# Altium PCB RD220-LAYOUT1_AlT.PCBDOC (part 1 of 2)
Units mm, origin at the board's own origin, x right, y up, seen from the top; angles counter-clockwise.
Board outline 250 x 145 mm, 4 copper layers (TOP, Mid-Layer 1, Mid-Layer 2, BOTTOM), stack 0.711 mm thick; 98 components, 44 nets, 237 pads, 371 vias.
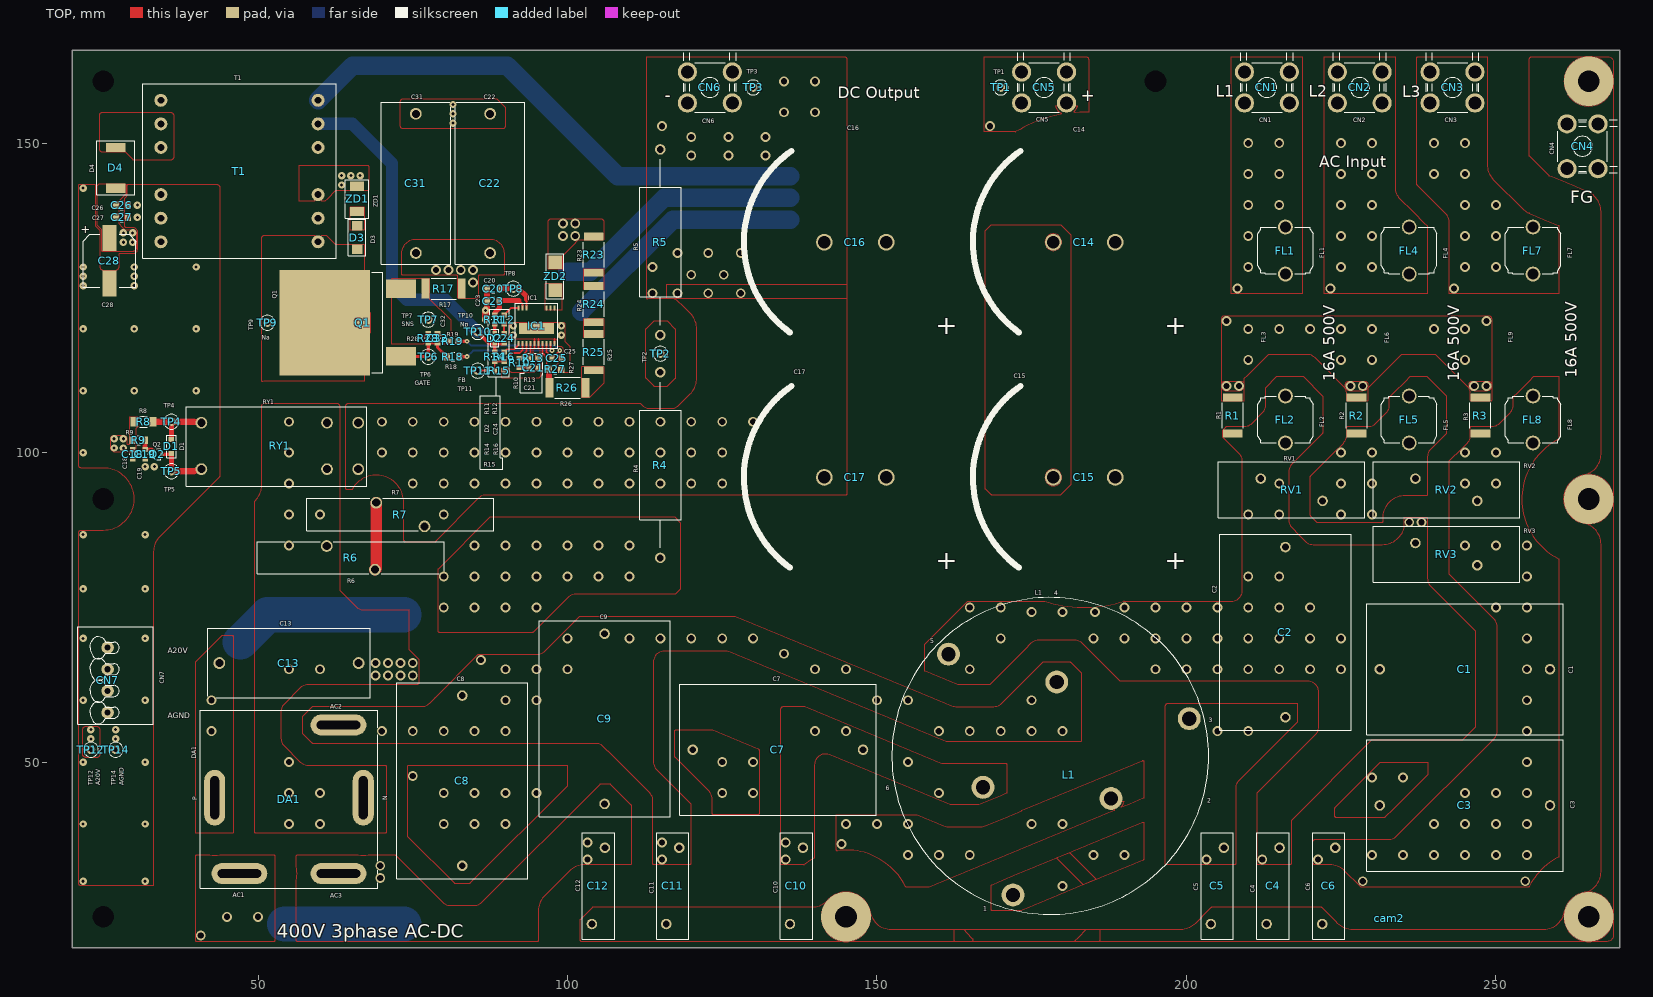
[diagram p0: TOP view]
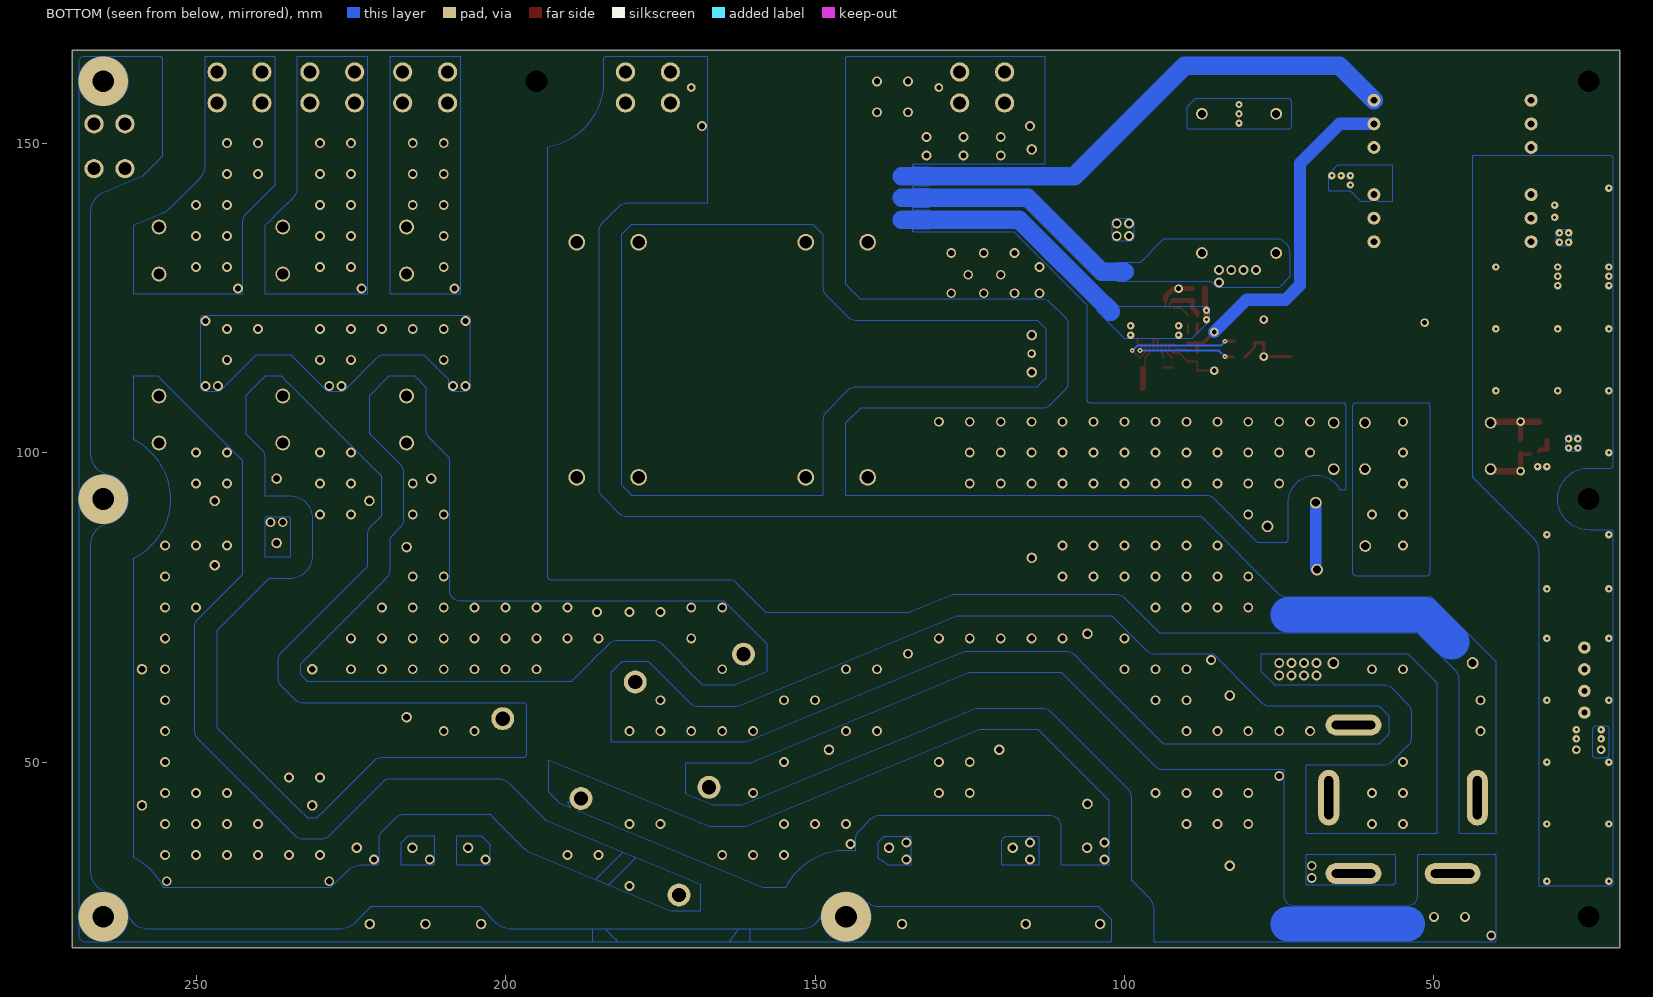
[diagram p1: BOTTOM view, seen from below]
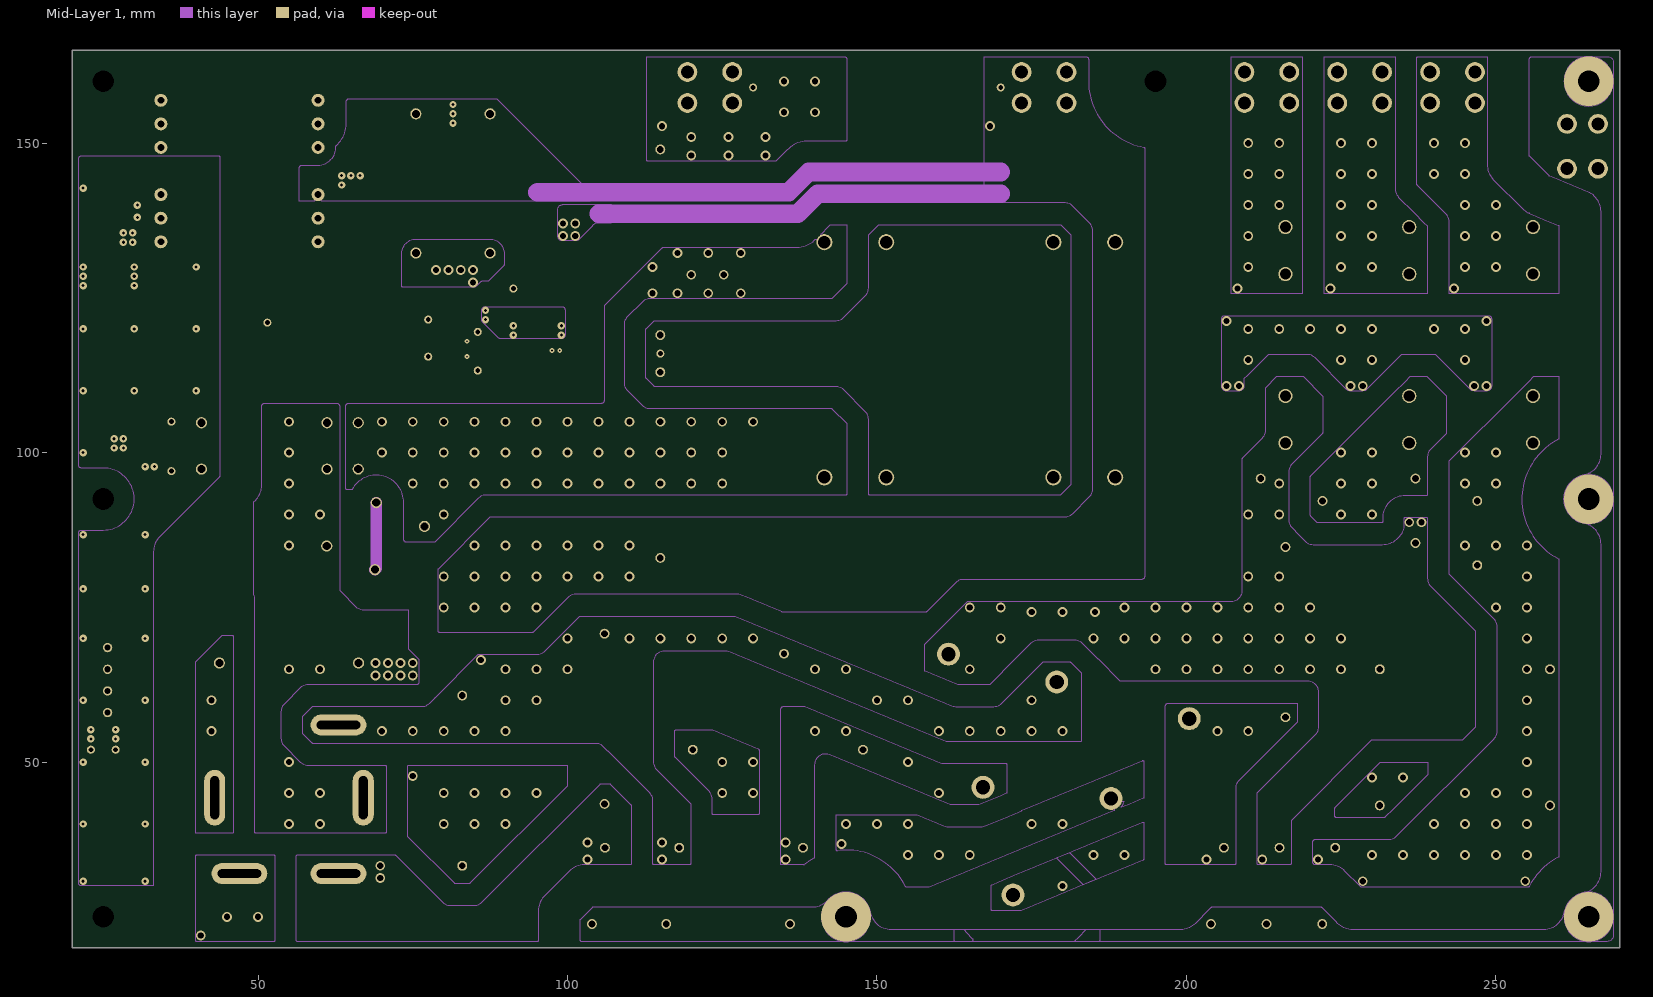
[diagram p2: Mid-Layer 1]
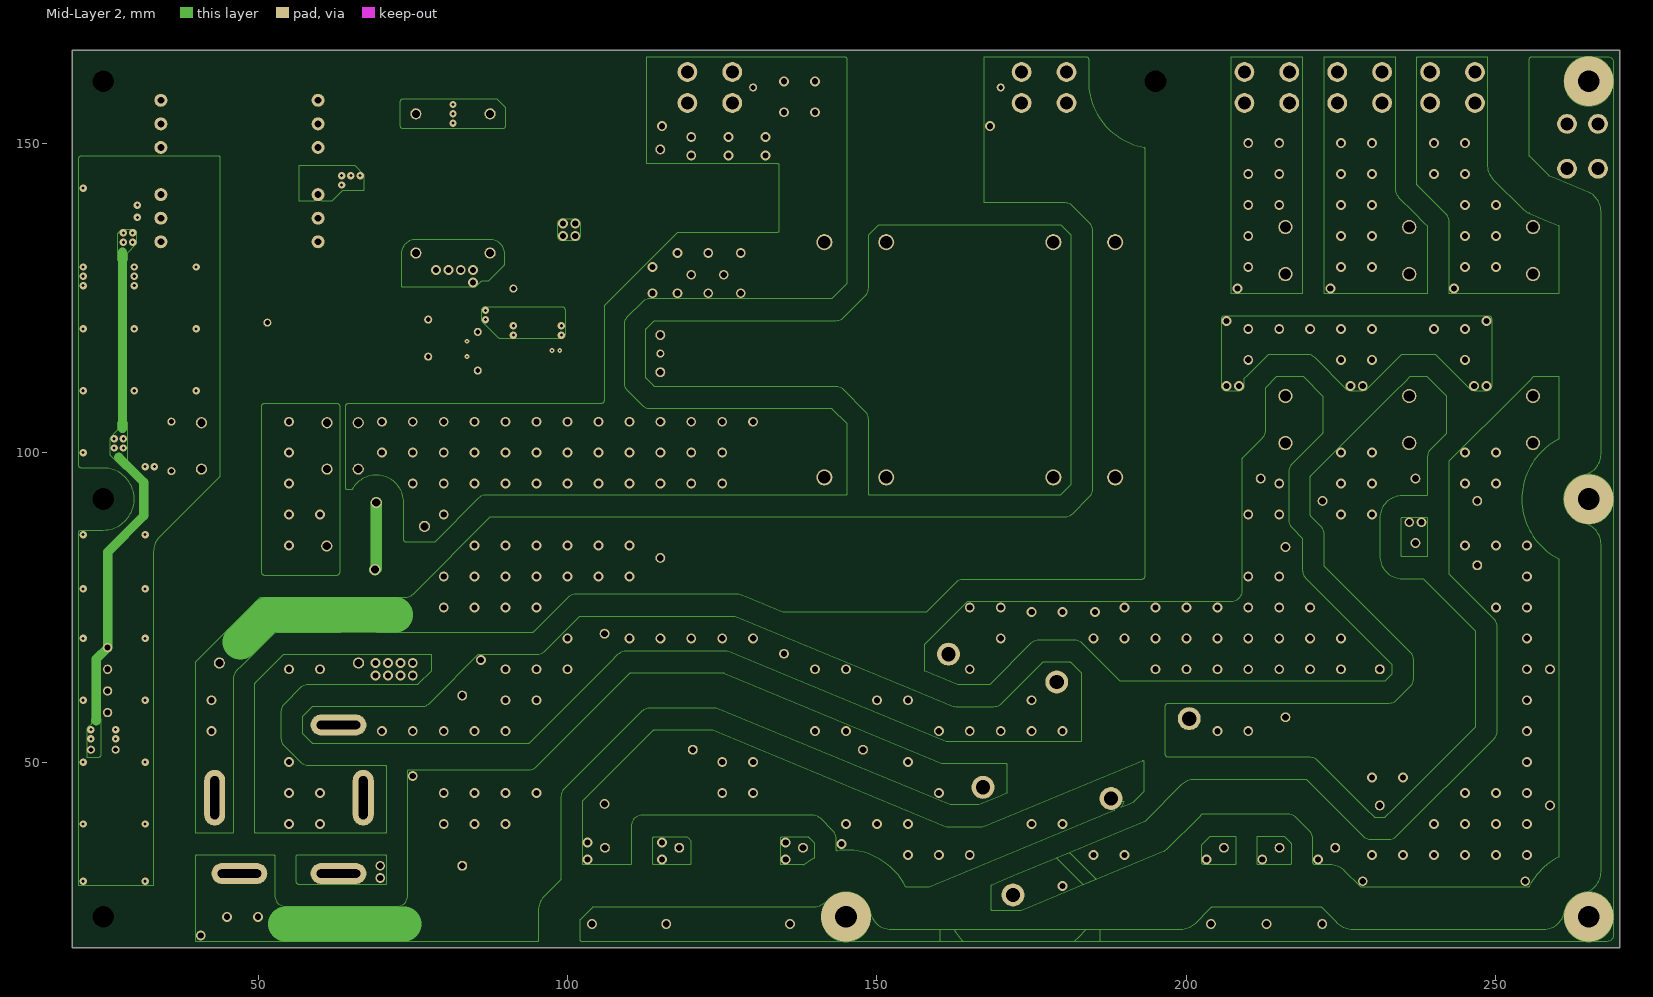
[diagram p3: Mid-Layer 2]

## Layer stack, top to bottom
Top Solder: solder mask 0.0102, Solder Resist, Dk 3.5
TOP: signal copper (thickness not stored)
Mid-Layer 1: signal copper 0.0356
Dielectric2: dielectric 0.32, FR-4, Dk 4.8
Mid-Layer 2: signal copper 0.0356
Dielectric3: dielectric 0.32, FR-4, Dk 4.8
BOTTOM: signal copper (thickness not stored)
Bottom Solder: solder mask 0.0102, Solder Resist, Dk 3.5

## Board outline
270,20 20,20 20,165 270,165

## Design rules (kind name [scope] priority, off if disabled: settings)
AssemblyTestPointUsage [All] p0: scope1count=1 scope1_0_kind=Board scope1_0_value=Board scope2count=1 scope2_0_kind=Board scope2_0_value=Board commentlength=0
AssemblyTestpoint [All] p0: scope1count=1 scope1_0_kind=Board scope1_0_value=Board scope2count=1 scope2_0_kind=Board scope2_0_value=Board commentlength=0
Clearance [All] p0: scope1count=1 scope1_0_kind=Board scope1_0_value=Board scope2count=1 scope2_0_kind=Board scope2_0_value=Board commentlength=0 gap=0.3
Clearance [All] p1: gap=0.3 ignorepadtopadclearanceinfootprint=TRUE except(0.5: Arc-Hole Track-Hole SMDPad-SMDPad SMDPad-Hole THPad-Hole Fill-Hole Poly-Hole Region-Hole Text-Hole; 0.75: Via-Hole; 1: SMDPad-THPad THPad-THPad)
ComponentClearance [All] p0: scope1count=1 scope1_0_kind=Board scope1_0_value=Board scope2count=1 scope2_0_kind=Board scope2_0_value=Board commentlength=0 gap=0.254 collisioncheckmode=3
DiffPairsRouting [All] p0: scope1count=1 scope1_0_kind=Board scope1_0_value=Board scope2count=1 scope2_0_kind=Board scope2_0_value=Board commentlength=0
FabricationTestPointUsage [All] p0: scope1count=1 scope1_0_kind=Board scope1_0_value=Board scope2count=1 scope2_0_kind=Board scope2_0_value=Board commentlength=0 valid=0 allowmultiple=FALSE
FabricationTestpoint [All] p0: scope1count=1 scope1_0_kind=Board scope1_0_value=Board scope2count=1 scope2_0_kind=Board scope2_0_value=Board commentlength=0 side=3 testpointundercomponent=TRUE minsize=1.016 maxsize=2.54 preferedsize=1.524 minholesize=0 maxholesize=1.016 preferedholesize=0.813 testpointgrid=0.025
FanoutControl Fanout_BGA [All] p0 off: scope1count=1 scope1_0_kind=Board scope1_0_value=Board scope2count=1 scope2_0_kind=Board scope2_0_value=Board commentlength=69 // Protel DXP Scope 1 Expression Was: IsBGA   Fanout_BGA (Default Rule)
FanoutControl Fanout_LCC [All] p0 off: scope1count=1 scope1_0_kind=Board scope1_0_value=Board scope2count=1 scope2_0_kind=Board scope2_0_value=Board commentlength=69 // Protel DXP Scope 1 Expression Was: IsLCC   Fanout_LCC (Default Rule)
FanoutControl Fanout_SOIC [All] p0 off: scope1count=1 scope1_0_kind=Board scope1_0_value=Board scope2count=1 scope2_0_kind=Board scope2_0_value=Board commentlength=71 // Protel DXP Scope 1 Expression Was: IsSOIC   Fanout_SOIC (Default Rule)
FanoutControl Fanout_Small [All] p0 off: scope1count=1 scope1_0_kind=Board scope1_0_value=Board scope2count=1 scope2_0_kind=Board scope2_0_value=Board commentlength=84 // Protel DXP Scope 1 Expression Was: (CompPinCount < 5)   Fanout_Small (Default Rule)
FanoutControl Fanout_Default [All] p0: scope1count=1 scope1_0_kind=Board scope1_0_value=Board scope2count=1 scope2_0_kind=Board scope2_0_value=Board commentlength=30 // Fanout_Default (Default Rule)
Height [All] p0: scope1count=1 scope1_0_kind=Board scope1_0_value=Board scope2count=1 scope2_0_kind=Board scope2_0_value=Board commentlength=0
HoleSize [All] p0: scope1count=1 scope1_0_kind=Board scope1_0_value=Board scope2count=1 scope2_0_kind=Board scope2_0_value=Board commentlength=0 absolutevalues=TRUE maxlimit=100 minlimit=0.001 maxpercent=80.000 minpercent=20.000
HoleSize [All] p1: absolutevalues=TRUE maxlimit=100 minlimit=0.001 maxpercent=80.000 minpercent=20.000
HoleToHoleClearance [All] p0: scope1count=1 scope1_0_kind=Board scope1_0_value=Board scope2count=1 scope2_0_kind=Board scope2_0_value=Board commentlength=0
HoleToHoleClearance [All] p1: gap=0.7 allowstackedmicrovias=FALSE
LayerPairs [All] p0: scope1count=1 scope1_0_kind=Board scope1_0_value=Board scope2count=1 scope2_0_kind=Board scope2_0_value=Board commentlength=0 enforce=TRUE
MinimumSolderMaskSliver [All] p0: scope1count=1 scope1_0_kind=Board scope1_0_value=Board scope2count=1 scope2_0_kind=Board scope2_0_value=Board commentlength=0
MinimumSolderMaskSliver [All] p1: minsoldermaskwidth=0.2
NetAntennae [All] p0: scope1count=1 scope1_0_kind=Board scope1_0_value=Board scope2count=1 scope2_0_kind=Board scope2_0_value=Board commentlength=0
NetAntennae [All] p1: netantennaetolerance=100
PasteMaskExpansion [All] p0: scope1count=1 scope1_0_kind=Board scope1_0_value=Board scope2count=1 scope2_0_kind=Board scope2_0_value=Board commentlength=0 expansion=0
PlaneClearance [All] p0: scope1count=1 scope1_0_kind=Board scope1_0_value=Board scope2count=1 scope2_0_kind=Board scope2_0_value=Board commentlength=0 clearance=0.001
PlaneClearance [All] p1: clearance=0.001
PlaneConnect [All] p0: scope1count=1 scope1_0_kind=Board scope1_0_value=Board scope2count=1 scope2_0_kind=Board scope2_0_value=Board commentlength=0 planeconnectstyle=Direct reliefexpansion=0.508 reliefentries=4 reliefconductorwidth=0.254 reliefairgap=0.254
PlaneConnect [All] p1: planeconnectstyle=Direct reliefexpansion=0.508 reliefentries=4 reliefconductorwidth=0.254 reliefairgap=0.254
PolygonConnect [All] p0: scope1count=1 scope1_0_kind=Board scope1_0_value=Board scope2count=1 scope2_0_kind=Board scope2_0_value=Board commentlength=0 connectstyle=Direct reliefconductorwidth=0.254 reliefentries=4 polygonreliefangle="90 Angle"
PolygonConnect [All] p1: connectstyle=Direct reliefconductorwidth=0.254 reliefentries=4 polygonreliefangle="90 Angle" airgapwidth=0.254
RoutingCorners [All] p0: scope1count=1 scope1_0_kind=Board scope1_0_value=Board scope2count=1 scope2_0_kind=Board scope2_0_value=Board commentlength=0 cornerstyle=45-Degree minsetback=2.54 maxsetback=2.54
RoutingLayers [All] p0: scope1count=1 scope1_0_kind=Board scope1_0_value=Board scope2count=1 scope2_0_kind=Board scope2_0_value=Board commentlength=0 top layer=Automatic mid layer 1=Automatic mid layer 2=Automatic bottom layer=Automatic
RoutingPriority [All] p0: scope1count=1 scope1_0_kind=Board scope1_0_value=Board scope2count=1 scope2_0_kind=Board scope2_0_value=Board commentlength=0
RoutingTopology [All] p0: scope1count=1 scope1_0_kind=Board scope1_0_value=Board scope2count=1 scope2_0_kind=Board scope2_0_value=Board commentlength=0 topology=Shortest
RoutingVias [All] p0: scope1count=1 scope1_0_kind=Board scope1_0_value=Board scope2count=1 scope2_0_kind=Board scope2_0_value=Board commentlength=0 holewidth=0.1 width=0.1 viastyle="Through Hole" minholewidth=0.001 minwidth=0.001 maxholewidth=100 maxwidth=100
RoutingVias [All] p1: holewidth=0.1 width=0.1 viastyle="Through Hole" minholewidth=0.001 minwidth=0.001 maxholewidth=100 maxwidth=100
ShortCircuit [All] p0: scope1count=1 scope1_0_kind=Board scope1_0_value=Board scope2count=1 scope2_0_kind=Board scope2_0_value=Board commentlength=0 allowed=FALSE
SilkToBoardRegionClearance [All] p0: scope1count=1 scope1_0_kind=Board scope1_0_value=Board scope2count=1 scope2_0_kind=Board scope2_0_value=Board commentlength=0
SilkToSilkClearance [All] p0: scope1count=1 scope1_0_kind=Board scope1_0_value=Board scope2count=1 scope2_0_kind=Board scope2_0_value=Board commentlength=0
SilkToSilkClearance [All] p1: silktosilkclearance=0.001
SilkToSolderMaskClearance [All] p0 off: scope1count=1 scope1_0_kind=Board scope1_0_value=Board scope2count=1 scope2_0_kind=Board scope2_0_value=Board commentlength=44 // Protel DXP Scope 1 Expression Was: IsPad
SilkToSolderMaskClearance [IsPad] p1: minsilkscreentomaskgap=0.1 clearancetoexposedcopper=TRUE
SolderMaskExpansion [All] p0: scope1count=1 scope1_0_kind=Board scope1_0_value=Board scope2count=1 scope2_0_kind=Board scope2_0_value=Board commentlength=0 expansion=0.001
SolderMaskExpansion [All] p1: expansion=0.001
UnRoutedNet [All] p0: scope1count=1 scope1_0_kind=Board scope1_0_value=Board scope2count=1 scope2_0_kind=Board scope2_0_value=Board commentlength=0
UnpouredPolygon [All] p0: scope1count=1 scope1_0_kind=Board scope1_0_value=Board scope2count=1 scope2_0_kind=Board scope2_0_value=Board commentlength=0
Width [All] p0: scope1count=1 scope1_0_kind=Board scope1_0_value=Board scope2count=1 scope2_0_kind=Board scope2_0_value=Board commentlength=0 maxlimit=1000 minlimit=2539.975 preferedwidth=0
Width [All] p1: maxlimit=1000 minlimit=2539.975 preferedwidth=0 toplayer_minwidth=0 midlayer1_minwidth=0 midlayer2_minwidth=0 bottomlayer_minwidth=0 minimp=50.000000 maximp=50.000000 favimp=50.000000
22 further rules are at their usual default settings.

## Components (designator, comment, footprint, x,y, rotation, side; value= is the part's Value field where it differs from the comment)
C1 "Ta-C0006DD" Ta-C0006DD 245,65 r180 top
C2 "Ta-C0006DD" Ta-C0006DD 216,71 r90 top
C3 "Ta-C0006DD" Ta-C0006DD 245,43 r180 top
C4 "Ta-C0001DD" Ta-C0001DD 214,30 r90 top
C5 "Ta-C0001DD" Ta-C0001DD 205,30 r90 top
C6 "Ta-C0001DD" Ta-C0001DD 223,30 r90 top
C7 "Ta-C0006DD" Ta-C0006DD 134,52 r0 top
C8 "Ta-C0006DD" Ta-C0006DD 83,47 r270 top
C9 "Ta-C0006DD" Ta-C0006DD 106,57 r90 top
C10 "Ta-C0001DD" Ta-C0001DD 137,30 r90 top
C11 "Ta-C0001DD" Ta-C0001DD 117,30 r90 top
C12 "Ta-C0001DD" Ta-C0001DD 105,30 r90 top
C13 "Ta-C0005DD" Ta-C0005DD 55,66 r180 top
C14 "Ta-CE0001DD" Ta-CE0001DD 183.5,134 r180 top
C15 "Ta-CE0001DD" Ta-CE0001DD 183.5,96 r180 top
C16 "Ta-CE0001DD" Ta-CE0001DD 146.5,134 r180 top
C17 "Ta-CE0001DD" Ta-CE0001DD 146.5,96 r180 top
C18 "Ta-C0001RR" Ta-C0001RR 29.75,99.75 r90 top
C19 "Ta-C0001RR" Ta-C0001RR 31.75,99.75 r90 top
C20 "Ta-C0002RR" Ta-C0002RR 88,126.5 r0 top
C21 "Ta-C0001RR" Ta-C0001RR 94.5,113.75 r180 top
C22 "Ta-C0005DD" Ta-C0005DD 87.5,143.5 r90 top
C23 "Ta-C0002RR" Ta-C0002RR 88,124.5 r0 top
C24 "Ta-C0001RR" Ta-C0001RR 89.75,118.5 r270 top
C25 "Ta-C0001RR" Ta-C0001RR 98.25,115.25 r180 top
C26 "Ta-C0002RR" Ta-C0002RR 28,140 r180 top
C27 "Ta-C0002RR" Ta-C0002RR 28,138 r180 top
C28 "Ta-CE0002RR" Ta-CE0002RR 26,131 r270 top
C31 "Ta-C0005DD" Ta-C0005DD 75.5,143.5 r90 top
C32 "Ta-C0001RR" Ta-C0001RR 79,118.5 r270 top
cam2 "Logo-Toshiba" Logo-Toshiba 232.8,24.8 r0 top
CN1 "Ta-CN0004DD(OT-005+OT-006)" Ta-CN0004DD(OT-005+OT-006) 213,159 r90 top
CN2 "Ta-CN0004DD(OT-005+OT-006)" Ta-CN0004DD(OT-005+OT-006) 228,159 r90 top
CN3 "Ta-CN0004DD(OT-005+OT-006)" Ta-CN0004DD(OT-005+OT-006) 243,159 r90 top
CN4 "Ta-CN0004DD(OT-005+OT-006)" Ta-CN0004DD(OT-005+OT-006) 264,149.5 r0 top
CN5 "Ta-CN0004DD(OT-005+OT-006)" Ta-CN0004DD(OT-005+OT-006) 177,159 r90 top
CN6 "Ta-CN0004DD(OT-005+OT-006)" Ta-CN0004DD(OT-005+OT-006) 123,159 r90 top
CN7 "Ta-CN0002DD" Ta-CN0002DD 27,64 r270 top
D1 "Ta-D0002RR" Ta-D0002RR 36,101 r270 top
D2 "Ta-D0001RR" Ta-D0001RR 88.25,118.5 r270 top
D3 "Ta-D0005RR" Ta-D0005RR 66,134.75 r270 top
D4 "Ta-D0006RR" Ta-D0006RR 27,146 r90 top
DA1 "Ta-DA0001DD" Ta-DA0001DD 55,44 r270 top
FL1 "Ta-FL0001DD" Ta-FL0001DD 216,119 r270 top
FL2 "Ta-FL0001DD" Ta-FL0001DD 216,119 r90 top
FL4 "Ta-FL0001DD" Ta-FL0001DD 236,119 r270 top
FL5 "Ta-FL0001DD" Ta-FL0001DD 236,119 r90 top
FL7 "Ta-FL0001DD" Ta-FL0001DD 256,119 r270 top
FL8 "Ta-FL0001DD" Ta-FL0001DD 256,119 r90 top
IC1 "Ta-IC0002RR_70" Ta-IC0002RR_70 95,120.5 r180 top
L1 "Ta-L0001DD" Ta-L0001DD 178,51 r180 top
Q1 "Ta-FET0003RR" Ta-FET0003RR 64.5,121 r90 top
Q2 "Ta-Q0001RR" Ta-Q0001RR 33.75,99.75 r270 top
R1 "Ta-R0007RR" Ta-R0007RR 207.5,106 r270 top
R2 "Ta-R0007RR" Ta-R0007RR 227.5,106 r270 top
R3 "Ta-R0007RR" Ta-R0007RR 247.5,106 r270 top
R4 "Ta-R0001DD" Ta-R0001DD 115,98 r270 top
R5 "Ta-R0001DD" Ta-R0001DD 115,134 r270 top
R6 "Ta-TH0001DD" Ta-TH0001DD 65,83 r0 top
R7 "Ta-TH0001DD" Ta-TH0001DD 73,90 r0 top
R8 "Ta-R0004RR" Ta-R0004RR 31.5,105 r0 top
R9 "Ta-R0003RR" Ta-R0003RR 30.75,102 r180 top
R10 "Ta-R0005RR" Ta-R0005RR 92.25,114.5 r270 top
R11 "Ta-R0005RR" Ta-R0005RR 88.25,121.5 r270 top
R12 "Ta-R0005RR" Ta-R0005RR 89.75,121.5 r90 top
R13 "Ta-R0005RR" Ta-R0005RR 94.5,115.25 r0 top
R14 "Ta-R0005RR" Ta-R0005RR 88.25,115.5 r270 top
R15 "Ta-R0005RR" Ta-R0005RR 89,113.25 r0 top
R16 "Ta-R0005RR" Ta-R0005RR 89.75,115.5 r90 top
R17 "Ta-R0007RR" Ta-R0007RR 80,126.5 r0 top
R18 "Ta-R0003RR" Ta-R0003RR 81.5,115.5 r0 top
R19 "Ta-R0005RR" Ta-R0005RR 81.5,118 r0 top
R23 "Ta-R0007RR" Ta-R0007RR 104.25,132 r270 top
R24 "Ta-R0007RR" Ta-R0007RR 104.25,124 r270 top
R25 "Ta-R0007RR" Ta-R0007RR 104.25,116.25 r270 top
R26 "Ta-R0007RR" Ta-R0007RR 100,110.5 r180 top
R27 "Ta-R0003RR" Ta-R0003RR 98,113.5 r0 top
R28 "Ta-R0005RR" Ta-R0005RR 77.5,118.5 r90 top
RV1 "Ta-RV0002DD" Ta-RV0002DD 217,94 r180 top
RV2 "Ta-RV0002DD" Ta-RV0002DD 242,94 r180 top
RV3 "Ta-RV0002DD" Ta-RV0002DD 242,83.6 r180 top
RY1 "Ta-RY0001DD" Ta-RY0001DD 53,101 r0 top
T1 "Ta-T0002DD" Ta-T0002DD 47,145.5 r90 top
TP1 "Ta-TP0001DD" Ta-TP0001DD 170,159 r0 top
TP2 "Ta-TP0001DD" Ta-TP0001DD 115,116 r0 top
TP3 "Ta-TP0001DD" Ta-TP0001DD 130,159 r0 top
TP4 "Ta-TP0001DD" Ta-TP0001DD 36,105 r90 top
TP5 "Ta-TP0001DD" Ta-TP0001DD 36,97 r90 top
TP6 "Ta-TP0001DD" Ta-TP0001DD 77.5,115.5 r180 top
TP7 "Ta-TP0001DD" Ta-TP0001DD 77.5,121.5 r180 top
TP8 "Ta-TP0001DD" Ta-TP0001DD 91.25,126.5 r180 top
TP9 "Ta-TP0001DD" Ta-TP0001DD 51.5,121 r90 top
TP10 "Ta-TP0001DD" Ta-TP0001DD 85.5,119.5 r180 top
TP11 "Ta-TP0001DD" Ta-TP0001DD 85.5,113.25 r180 top
TP12 "Ta-TP0001DD" Ta-TP0001DD 23,52 r90 top
TP14 "Ta-TP0001DD" Ta-TP0001DD 27,52 r90 top
ZD1 "Ta-D0004RR" Ta-D0004RR 66,141 r90 top
ZD2 "Ta-D0007RR" Ta-D0007RR 98,128.5 r270 top

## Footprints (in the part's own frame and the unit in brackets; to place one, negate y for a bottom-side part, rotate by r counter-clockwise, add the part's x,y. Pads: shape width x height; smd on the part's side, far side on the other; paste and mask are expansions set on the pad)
Logo-Toshiba [mm] "KC00080BKP"
Ta-C0001DD [mm] "KC00080BKP"
  round 1.7 / inner round 1.6 / far side round 1.7 hole 1.1 paste-1.9 mask+0: 1(-6.161,1.05) 2(6.161,-1.05)
  silkscreen extent -8.6,-2.6 8.6,2.6
Ta-C0001RR [mm] "KC00080BKP"
  rect 0.8x0.9 smd paste-1 mask+0: 1(-0.75,0) 2(0.75,0)
  silkscreen extent -0.06,-0.5 0.06,0.5
Ta-C0002RR [mm] "KC00080BKP"
  rect 1x1.2 smd paste-1.3 mask+0: 1(-1,0) 2(1,0)
  silkscreen extent -0.25,-0.72 0.25,0.72
Ta-C0005DD [mm] "KC00080BKP"
  round 1.9 / inner round 1.8 / far side round 1.9 hole 1.3 paste-2.1 mask+0: 1(-11.25,0) 2(11.25,0)
  silkscreen extent -13.1,-5.6 13.1,5.6
Ta-C0006DD [mm] "KC00080BKP"
  round 1.7 / inner round 1.6 / far side round 1.7 hole 1.1 paste-1.9 mask+0: 1(-13.75,0) 2(13.75,0)
  silkscreen extent -15.85,-10.6 15.85,10.6
Ta-CE0001DD [mm] "KC00080BKP"
  round 2.7 / inner round 2.6 / far side round 2.7 hole 2 paste-2.9 mask+0: 1(5,0) 2(-5,0)
  silkscreen extent 10.32,-14.74 18,14.56
Ta-CE0002RR [mm] "KC00080BKP"
  rect 4.2x2.2 smd paste-4.3 mask+0: 1(3.65,0) 2(-3.65,0)
  silkscreen extent -4.25,-4.25 4.25,4.25
Ta-CN0002DD [mm] "KC00080BKP"
  round 2 / inner round 1.5 / far side round 2 hole 1 paste-2.2 mask+0: 1(-4.5,-1.3) 2(-1,-1.3) 3(2.5,-1.3) 4(6,-1.3)
  silkscreen extent -7.85,-6.1 7.85,6.1
Ta-CN0004DD(OT-005+OT-006) [mm] "KC00080BKP"
  round 3.1 / inner round 3.2 / far side round 3.1 hole 2.1 paste-3.3 mask+0: 1(-2.5,-3.625) 2(2.5,-3.625) 3(2.5,3.625) 4(-2.5,3.625)
  silkscreen extent -4,-4.25 5.6,4.25
Ta-D0001RR [mm] "KC00080BKP"
  rect 0.6x0.8 smd paste-0.9 mask+0: A(0.85,0) C(-0.85,0)
  silkscreen extent -1.43,-0.67 1.42,0.68
Ta-D0002RR [mm] "KC00080BKP"
  rect 0.8x0.9 smd paste-1 mask+0: A(1.15,0) C(-1.15,0)
  silkscreen extent -1.85,-0.75 1.85,0.75
Ta-D0004RR [mm] "KC00080BKP"
  rect 1.52x2.2 smd paste-2.3 mask+0: A(2.035,0) C(-2.035,0)
  silkscreen extent -3.1,-1.91 3.1,1.91
Ta-D0005RR [mm] "KC00080BKP"
  rect 1.52x1.68 smd paste-1.78 mask+0: A(1.88,0) C(-1.88,0)
  silkscreen extent -2.94,-1.43 2.94,1.43
Ta-D0006RR [mm] "KC00080BKP"
  rect 1.52x3.2 smd paste-3.3 mask+0: A(3.305,0) C(-3.305,0)
  silkscreen extent -4.37,-3.05 4.37,3.05
Ta-D0007RR [mm] "KC00080BKP"
  rect 2.2x2.21 smd paste-2.31 mask+0: A(2.25,0) C(-2.25,0)
  silkscreen extent -3.65,-1.4 3.65,1.41
Ta-DA0001DD [mm] "KC00080BKP"
  oval 3.4x9 hole 1.4 slot 7 at 90 deg paste-9.2 mask+0: AC1(12,-8) AC2(-12,8) AC3(12,8)
  oval 9x3.4 hole 1.4 slot 7 at 0 deg paste-9.2 mask+0: N(-0.25,12) P(-0.25,-12)
  silkscreen extent -14.35,-14.35 14.35,14.35
Ta-FET0003RR [mm] "KC00080BKP"
  rect 17x14.6 smd paste-17.1 mask+0: D(0,3.7)
  rect 3x4.8 smd paste-4.9 mask+0: G(-5.45,-8.6) S(5.45,-8.6)
  silkscreen extent -8.11,-5.68 8.11,-3.9
Ta-FL0001DD [mm] "KC00080BKP"
  round 2.4 / inner round 2.3 / far side round 2.4 hole 1.8 paste-2.6 mask+0: 1(-17.45,0) 2(-9.85,0)
  silkscreen extent -17.4,-4.49 -9.9,4.49
Ta-IC0002RR_70 [mm] "KC00080BKP"
  rect 0.35x0.8 smd paste-0.9 mask+0: 1(-2.925,-2.9) 2(-2.275,-2.9) 3(-1.625,-2.9) 8(1.625,-2.9) 9(2.275,-2.9) 10(2.925,-2.9) 11(2.925,2.9) 12(2.275,2.9) 13(1.625,2.9) 14(0.975,2.9) 15(0.325,2.9) 16(-0.325,2.9) 17(-0.975,2.9) 18(-1.625,2.9) 19(-2.275,2.9) 20(-2.925,2.9)
  rect 5.68x1.78 smd paste-5.78 mask+0: 21(0,0.47)
  silkscreen extent -3.45,-3.65 3.45,3.65
Ta-L0001DD [mm] "KC00080BKP"
  round 3.7 hole 2.3 paste-3.9 mask+0: 1(6.018,22.458) 2(-9.83,6.883) 3(-22.458,-6.018) 4(-1.046,-11.954) 5(16.44,-16.44) 6(10.876,5.071)
  silkscreen extent -25.6,-25.6 25.6,25.6
Ta-Q0001RR [mm] "KC00080BKP"
  rect 0.6x0.6 smd paste-0.7 mask+0: B(-0.5,-0.7) C(0,0.7) E(0.5,-0.7)
  silkscreen extent -0.9,-0.13 0.9,0.5
Ta-R0001DD [mm] "KC00080BKP"
  round 1.7 / inner round 1.6 / far side round 1.7 hole 1.1 paste-1.9 mask+0: 1(-15,0) 2(15,0)
  silkscreen extent -13.4,-3.35 13.4,3.35
Ta-R0003RR [mm] "KC00080BKP"
  rect 1x1.2 smd paste-1.3 mask+0: 1(-1,0) 2(1,0)
  silkscreen extent -0.25,-0.72 0.25,0.72
Ta-R0004RR [mm] "KC00080BKP"
  rect 1.2x1.6 smd paste-1.7 mask+0: 1(-1.5,0) 2(1.5,0)
  silkscreen extent -0.63,-0.9 0.63,0.9
Ta-R0005RR [mm] "KC00080BKP"
  rect 0.8x0.9 smd paste-1 mask+0: 1(-0.75,0) 2(0.75,0)
  silkscreen extent -0.06,-0.5 0.06,0.5
Ta-R0007RR [mm] "KC00080BKP"
  rect 1.25x3.2 smd paste-3.3 mask+0: 1(-2.925,0) 2(2.925,0)
  silkscreen extent -2.03,-1.7 2.03,1.7
Ta-RV0002DD [mm] "KC00080BKP"
  round 1.7 / inner round 1.6 / far side round 1.7 hole 1.1 paste-1.9 mask+0: 1(-5,1.8) 2(5,-1.8)
  silkscreen extent -11.85,-4.5 11.85,4.5
Ta-RY0001DD [mm] "KC00080BKP"
  round 1.9 / inner round 1.8 / far side round 1.9 hole 1.3 paste-2.1 mask+0: 11-1(8.15,3.83) 11-2(8.15,-3.67) 14-1(13.19,3.83) 14-2(13.19,-3.67) A1(-12.15,3.83) A2(-12.15,-3.67)
  silkscreen extent -14.6,-6.45 14.6,6.45
Ta-T0002DD [mm] "KC00080BKP"
  round 2.1 hole 1.1 paste-2.3 mask+0: 1(-11.43,-12.7) 2(-7.62,-12.7) 3(-3.81,-12.7) 4(3.81,-12.7) 5(7.62,-12.7) 6(11.43,-12.7) 7(11.43,12.7) 8(7.62,12.7) 9(3.81,12.7) 10(-3.81,12.7) 11(-7.62,12.7) 12(-11.43,12.7)
  silkscreen extent -14.1,-15.6 14.1,15.6
Ta-TH0001DD [mm] "KC00080BKP"
  round 1.9 / inner round 1.8 / far side round 1.9 hole 1.3 paste-2.1 mask+0: 1(-3.9,1.91) 2(3.9,-1.91)
  silkscreen extent -15.1,-2.6 15.1,2.6
Ta-TP0001DD [mm] "KC00080BKP"
  round 1.4 / inner round 1.3 / far side round 1.4 hole 0.8 paste-1.6 mask+0: 1(0,0)
  silkscreen extent -1.2,-1.2 1.2,1.2

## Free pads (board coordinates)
  round 0 hole 3.5 unplated paste-3.5 mask+0: ""(25,25) ""(25,92.5) ""(25,160) ""(195,160)

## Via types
v1: diameter 1.6, hole 1, TOP to BOTTOM, 305 vias
v2: diameter 1.2, hole 0.5, TOP to BOTTOM, 58 vias
v3: diameter 8, hole 3.5, TOP to BOTTOM, 4 vias
v4: diameter 0.8, hole 0.3, TOP to BOTTOM, 4 vias

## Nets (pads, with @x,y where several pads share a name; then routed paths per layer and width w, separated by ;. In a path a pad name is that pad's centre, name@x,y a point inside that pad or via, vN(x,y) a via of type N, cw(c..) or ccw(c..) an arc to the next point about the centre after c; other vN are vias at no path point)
GND_A: C18.1 C19.1 C26.1 C27.1 C28.1 CN7.4 Q2.E T1.10 T1.11 TP14.1
  other v2: 21.75,30.75 31.75,30.75 21.75,40 31.75,40 21.75,50 31.75,50 27,53.75 27,55.25 21.75,60 31.75,60 21.75,70 31.75,70 21.75,78 31.75,78 21.75,86.75 31.75,86.75 31.75,97.75 33.25,97.75 21.75,100 21.75,110 30,110 40,110 21.75,120 30,120 40,120 21.75,127 30,127 21.75,128.5 30,128.5 21.75,130 30,130 40,130 30.5,138 30.5,140 21.75,142.75
GND_DC: C16.1 C17.1 C20.1 C21.1 C22.1 C23.1 C25.1 C31.1 CN6.1 CN6.2 CN6.3 CN6.4 IC1.15 IC1.16 IC1.20 IC1.21 R5.1 R7.2 R13.2 R15.2 R17.2 R27.2 RY1.14-1 RY1.14-2 T1.6 TP3.1 | length 176
  TOP w0.3: 94.675,116.8 IC1.15@94.675,117.6 94.675,118.4 ; 95.325,116.8 IC1.16@95.325,117.6 95.325,118.4 ; IC1.20@97.925,117.6 97.925,118.4
  TOP w1: v2(86.75,123) 87,123.25 C23.1@87,124.5 C20.1@87,126.5
  TOP w1.1: v2(86.75,121.5) v2(86.75,123)
  BOTTOM w3: T1.6@59.7,156.93 65.27,162.5 90.286,162.5 108.136,144.65 136,144.65 ; 100,129.2 103.652,129.2 115.602,141.15 136,141.15 ; 102.201,122.799 117.052,137.65 136,137.65
  other v1: 80,90 75,95 80,95 85,95 90,95 95,95 100,95 105,95 110,95 115,95 120,95 125,95 70,100 75,100 80,100 85,100 90,100 95,100 100,100 105,100 110,100 115,100 120,100 125,100 70,105 75,105 80,105 85,105 90,105 95,105 100,105 105,105 110,105 115,105 120,105 125,105 130,105 113.75,125.75 117.75,125.75 122.75,125.75 128,125.75 84.75,127.5 120,128.75 125.25,128.75 78.75,129.5 80.75,129.5 82.75,129.5 84.75,129.5 113.75,130 117.75,132.25 122.75,132.25 128,132.25 120,148 126,148 132,148 120,151 126,151 132,151 115.25,152.75 135,155 140,155 135,160 140,160
  other v2: 91.25,119 99,119 91.25,120.5 99,120.5
GND_F: C4.1 C5.1 C6.1 C10.1 C11.1 C12.1 CN4.1 CN4.2 CN4.3 CN4.4
  other v3: 145,25 265,25 265,92.5 265,160
L1: CN1.1 CN1.2 CN1.3 CN1.4 FL1.1 FL1.2
  other v1: 208.25,126.5 210,130 210,135 210,140 215,140 210,145 215,145 210,150 215,150
L1f: C1.2 C2.2 C4.2 FL2.1 FL2.2 L1.5 R1.2 RV1.2 RV3.2
  other v1: 212.25,34.25 165,65 195,65 200,65 205,65 210,65 215,65 220,65 225,65 170,70 185,70 190,70 195,70 200,70 205,70 210,70 215,70 220,70 225,70 175,74.25 180,74.25 185.25,74.25 165,75 170,75 190,75 195,75 200,75 205,75 210,75 215,75 220,75 210,80 215,80 236,88.75 238,88.75 210,90 215,90 215,95
L1r: C7.2 C8.2 C10.2 DA1.AC1 L1.6 | length 38.4
  Mid-Layer 2 w5.7: 54.5,23.85 73.6,23.85
  BOTTOM w5.7: 54.3,23.85 73.6,23.85
  other v1: 40.75,22 45,25 50,25 135.25,34.25 135.25,37 80,40 85,40 90,40 80,45 85,45 90,45 95,45 160,45 75,47.75 155,50 140,55 145,55
L2: CN2.1 CN2.2 CN2.3 CN2.4 FL4.1 FL4.2
  other v1: 223.25,126.5 225,130 230,130 225,135 230,135 225,140 230,140 225,145 230,145 225,150 230,150
L2f: C2.1 C3.2 C5.2 FL5.1 FL5.2 L1.3 R2.2 RV1.1 RV2.2
  other v1: 203.25,34.25 230,47.5 235,47.5 205,55 210,55 225,90 230,90 225,95 230,95 225,100 230,100
L2r: C8.1 C9.2 C11.2 DA1.AC2 L1.4
  other v1: 115.25,34.25 115.25,37 70,55 75,55 80,55 85,55 90,55 160,55 165,55 170,55 175,55 180,55 90,60 95,60 150,60 155,60 175,60 90,65 95,65 100,65 140,65 145,65 86,66.5 135,67.5 100,70 110,70 115,70 120,70 125,70 130,70
L3: CN3.1 CN3.2 CN3.3 CN3.4 FL7.1 FL7.2
  other v1: 243.25,126.5 245,130 250,130 245,135 250,135 245,140 250,140 240,145 245,145 240,150 245,150
L3f: C1.1 C3.1 C6.2 FL8.1 FL8.2 L1.1 R3.2 RV2.1 RV3.1
  other v1: 180,30 228.5,30.75 254.75,30.75 221.25,34.25 185,35 190,35 230,35 235,35 240,35 245,35 250,35 255,35 240,40 245,40 250,40 255,40 245,45 250,45 255,45 255,50 255,55 255,60 255,65 255,70 250,75 255,75 255,80 245,85 250,85 255,85 245,95 250,95 245,100 250,100
L3r: C7.1 C9.1 C12.2 DA1.AC3 L1.2
  other v1: 69.75,31.25 69.75,33.25 103.25,34.25 155,35 160,35 165,35 144.25,36.75 103.25,37 145,40 150,40 155,40 175,40 180,40 125,45 130,45 125,50 130,50
M: C14.1 C15.1 C16.2 C17.2 R4.1 R5.2 TP2.1
RDIS: R1.1 R2.1 R3.1
  other v1: 206.5,110.75 208.5,110.75 226.5,110.75 228.5,110.75 246.5,110.75 248.5,110.75 210,115 225,115 230,115 245,115 210,120 215,120 220,120 225,120 230,120 240,120 245,120 206.5,121.25 248.5,121.25
SIGN0021: C20.2 IC1.8 TP8.1 | length 6.8
  TOP w0.3: IC1.8@93.375,123.4 93.375,124.718
  TOP w0.8: C20.2@89,126.5 TP8.1@91.25,126.5 92.15,126.5 93.375,125.275 93.375,124.718
SIGN0023: IC1.13 R10.1 | length 2.8
  TOP w0.3: R10.1@92.25,115.25 93.375,116.375 IC1.13@93.375,117.6
SIGN0024: C21.2 R10.2 | length 1.5
  TOP w0.3: R10.2@92.25,113.75 C21.2@93.75,113.75
SIGN0029: C23.2 IC1.9 R11.1 | length 7.3
  TOP w0.3: 92.175,124.6 92.725,124.05 IC1.9@92.725,123.4
  TOP w0.8: R11.1@88.25,122.25 88.25,122.561 89,123.311 C23.2@89,124.5 89,124.6 92.175,124.6
SIGN00121: R6.2 R7.1 | length 43.6
  TOP w1.9: R6.2@68.9,81.09 69.1,81.29 R7.1@69.1,91.91
  Mid-Layer 1 w1.9: R6.2@68.9,81.09 69.1,81.29 R7.1@69.1,91.91
  Mid-Layer 2 w1.9: R6.2@68.9,81.09 69.1,81.29 R7.1@69.1,91.91
  BOTTOM w1.9: R6.2@68.9,81.09 69.1,81.29 R7.1@69.1,91.91
SIGN00122: C13.1 DA1.N R6.1 RY1.11-1 RY1.11-2
  other v1: 55,40 60,40 55,45 60,45 55,50 69,64 71,64 73,64 75,64 55,65 60,65 69,66 71,66 73,66 75,66 55,85 55,90 60,90 55,95 55,100 55,105
SIGN00123: D1.C R8.2 RY1.A1 TP4.1 | length 10.7
  TOP w0.8: D1.C@36,102.15 TP4.1@36,105
  TOP w1: R8.2@33,105 TP4.1@36,105 39.627,105 RY1.A1@40.85,104.83
SIGN00124: D1.A Q2.C RY1.A2 TP5.1 | length 9.3
  TOP w0.6: Q2.C@34.45,99.75 35.9,99.75 D1.A@36,99.85
  TOP w0.8: TP5.1@36,97 D1.A@36,99.85
  TOP w1: TP5.1@36,97 39.66,97 RY1.A2@40.85,97.33
SIGN00125: C19.2 Q2.B R9.1 | length 2.9
  TOP w0.6: C19.2@31.75,100.5 32.8,100.5 Q2.B@33.05,100.25
  TOP w0.8: C19.2@31.75,100.5 R9.1@31.75,102
SIGN00210: D2.C R11.2 | length 1.4
  TOP w0.6: D2.C@88.25,119.35 R11.2@88.25,120.75
SIGN00211: C24.2 D2.A R14.1 T1.5 TP10.1 | length 57.7
  TOP w0.6: TP10.1@85.5,119.5 87.35,117.65 D2.A@88.25,117.65 ; R14.1@88.25,116.25 D2.A@88.25,117.65 ; C24.2@89.75,117.75 89.65,117.65 D2.A@88.25,117.65
  BOTTOM w2: T1.5@59.7,153.12 65.272,153.12 71.65,146.742 71.65,127.064 74.014,124.7 80.3,124.7 TP10.1@85.5,119.5
SIGN00212: IC1.10 R12.2 | length 2.8
  TOP w0.3: R12.2@89.75,122.25 90.9,123.4 IC1.10@92.075,123.4
SIGN00213: C24.1 R12.1 | length 1.5
  TOP w0.3: C24.1@89.75,119.25 R12.1@89.75,120.75
SIGN00214: IC1.14 R13.1 | length 2.5
  TOP w0.3: R13.1@93.75,115.25 93.75,115.901 94.025,116.176 IC1.14@94.025,117.6
SIGN00218: IC1.11 R16.2 | length 3
  TOP w0.3: R16.2@89.75,116.25 90.2,116.7 91.394,116.7 92.075,117.381 IC1.11@92.075,117.6
SIGN00219: IC1.12 R14.2 R15.1 R16.1 TP11.1 | length 10.5
  TOP w0.3: TP11.1@85.5,113.25 R15.1@88.25,113.25 R14.2@88.25,114.75 R16.1@89.75,114.75 91.1,116.1 92.251,116.1 92.725,116.574 IC1.12@92.725,117.6
SIGN00220: C32.1 Q1.S R17.1 R19.1 R28.2 TP7.1
SIGN00222: IC1.19 R18.2 | length 16.6
  TOP w0.3: IC1.19@97.275,117.6 97.275,116.895 v4(97.5,116.5)
  TOP w0.5: R18.2@82.5,115.5 v4(83.75,115.5)
  BOTTOM w0.3: v4(83.75,115.5) 84.75,116.5 v4(97.5,116.5)
SIGN00223: C25.2 IC1.18 R19.2 | length 21.6
  TOP w0.3: IC1.18@96.625,117.6 96.625,116.244 97.5,115.369 C25.2@97.5,115.25 v4(98.75,116.5)
  TOP w0.5: R19.2@82.25,118 v4(83.75,118)
  BOTTOM w0.3: v4(83.75,118) 84.45,117.3 97.95,117.3 v4(98.75,116.5)
SIGN00224: D3.C ZD1.C
SIGN00225: D3.A Q1.D T1.1 TP9.1
SIGN00226: C32.2 Q1.G R18.1 R28.1 TP6.1 | length 11
  TOP w0.5: Q1.G@73.1,115.55 76.591,115.55 TP6.1@77.5,115.5 R28.1@77.5,117.75 C32.2@79,117.75 79,117 R18.1@80.5,115.5
SIGN00227: D4.A T1.8 T1.9
SIGN00230: IC1.1 IC1.2 IC1.3 ZD2.A
SIGN00231: R25.2 R26.1
SIGN00232: R23.2 R24.1
SIGN00233: R24.2 R25.1
SIGN00234: IC1.17 R26.2 R27.1 | length 7.6
  TOP w0.3: IC1.17@95.975,117.6 95.975,116.045 96.65,115.37 96.65,113.85 R27.1@97,113.5
  TOP w1: R27.1@97,113.5 97,110.575 R26.2@97.075,110.5
VDD20_A: C18.2 C26.2 C27.2 C28.2 CN7.1 D4.C R8.1 R9.2 TP12.1 | length 75.9
  Mid-Layer 2 w1.5: 23.85,56.664 23.85,66.65 CN7.1@25.7,68.5 25.7,83.937 31.55,89.787 31.55,95.213 27.489,99.275 ; 28.1,103.893 28.1,132.357
  other v2: 23,53.75 23,55.25 26.75,100.75 28.25,100.75 26.75,102.25 28.25,102.25 28.25,134 29.75,134 28.25,135.5 29.75,135.5
VP_DC: C13.2 C14.2 C15.2 C22.2 C31.2 CN5.1 CN5.2 CN5.3 CN5.4 DA1.P R4.2 R23.1 T1.3 TP1.1 ZD1.A ZD2.C | length 197.6
  Mid-Layer 1 w3: 95.15,142.1 135.741,142.1 138.991,145.35 170,145.35 ; 105.05,138.6 137.19,138.6 140.44,141.85 170,141.85
  Mid-Layer 2 w5.7: 47.144,69.394 51.54,73.79 72.2,73.79
  BOTTOM w5.7: 47.144,69.394 51.54,73.79 73.6,73.79
  other v1: 42.5,55 42.5,60 80,75 85,75 90,75 95,75 80,80 85,80 90,80 95,80 100,80 105,80 110,80 85,85 90,85 95,85 100,85 105,85 110,85 99.25,135 101.25,135 99.25,137 101.25,137 168.25,152.75
  other v2: 63.5,143.25 63.5,144.75 65,144.75 66.5,144.75 81.5,153.25 81.5,154.75 81.5,156.25
pads on no net: CN7.2 CN7.3 T1.2 T1.4 T1.7 T1.12

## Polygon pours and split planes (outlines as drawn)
no net on Top Overlay "TOPOVERLAY271" (solid, pour order 0): 45 vertices, not listed, extent 236.25,24.742 239.539,28.336
no net on Top Overlay "TOPOVERLAY272" (solid, pour order 0): 62 vertices, not listed, extent 249.612,24.805 252.605,28.279
no net on Top Overlay "TOPOVERLAY273" (solid, pour order 0): 36 vertices, not listed, extent 252.883,24.8 256.402,28.28
RDIS on TOP "TOP1" (solid, pour order 114): 205.85,108.3 cw(c205.85,108.45) 205.7,108.45 205.7,111.05 cw(c206.2,111.05) 206.2,111.55 208.8,111.55 cw(c208.8,111.05) 209.3,111.05 209.3,108.45 cw(c209.15,108.45) 209.15,108.3
SIGN00230 on TOP "TOP3" (solid, pour order 116): 96.55,123 cw(c96.55,123.15) 96.4,123.15 96.4,127.2 cw(c96.55,127.2) 96.55,127.35 98.95,127.35 cw(c98.95,127.2) 99.1,127.2 99.1,123.15 cw(c98.95,123.15) 98.95,123
SIGN00232 on TOP "TOP4" (solid, pour order 117): 102.8,126.3 cw(c102.8,126.45) 102.65,126.45 102.65,129.6 cw(c102.8,129.6) 102.8,129.75 105.7,129.75 cw(c105.7,129.6) 105.85,129.6 105.85,126.45 cw(c105.7,126.45) 105.7,126.3
SIGN00233 on TOP "TOP5" (solid, pour order 118): 102.8,118.55 cw(c102.8,118.7) 102.65,118.7 102.65,121.55 cw(c102.8,121.55) 102.8,121.7 105.7,121.7 cw(c105.7,121.55) 105.85,121.55 105.85,118.7 cw(c105.7,118.7) 105.7,118.55
SIGN00231 on TOP "TOP6" (solid, pour order 119): 102.45,108.9 cw(c102.45,109.05) 102.3,109.05 102.3,113.8 cw(c102.45,113.8) 102.45,113.95 105.7,113.95 cw(c105.7,113.8) 105.85,113.8 105.85,111.262 cw(c105.7,111.262) 105.806,111.156 103.594,108.944 cw(c103.488,109.05) 103.488,108.9
VP_DC on TOP "TOP7" (solid, pour order 120): 97.05,129.65 cw(c97.05,129.8) 96.9,129.8 96.9,137.3 cw(c97.4,137.3) 97.4,137.8 105.35,137.8 cw(c105.35,137.3) 105.85,137.3 105.85,134.45 cw(c105.7,134.45) 105.7,134.3 101.681,134.3 100.817,133.436 100.814,133.433 99.15,131.769 99.15,129.8 cw(c99,129.8) 99,129.65
GND_DC on TOP "TOP8" (solid, pour order 121): 25 vertices, not listed, extent 89.35,112 95.65,116.9
GND_DC on TOP "TOP9" (solid, pour order 122): 29 vertices, not listed, extent 90.7,112.9 100.4,121.05
SIGN00224 on TOP "TOP10" (solid, pour order 123): 65.05,135.9 cw(c65.05,136.05) 64.9,136.05 64.9,139.55 cw(c65.05,139.55) 65.05,139.7 67,139.7 cw(c67,139.55) 67.15,139.55 67.15,136.05 cw(c67,136.05) 67,135.9
GND_F on TOP "TOP11" (solid, pour order 124): 141,25 ccw(c145,25) 149,25 ccw(c145,25)
GND_F on TOP "TOP12" (solid, pour order 125): 162.65,21 cw(c162.65,21.15) 162.5,21.15 162.5,22.85 cw(c162.65,22.85) 162.65,23 185.85,23 cw(c185.85,22.85) 186,22.85 186,21.15 cw(c185.85,21.15) 185.85,21
GND_F on TOP "TOP13" (solid, pour order 126): 261,25 ccw(c265,25) 269,25 ccw(c265,25)
GND_F on TOP "TOP14" (solid, pour order 127): 261,92.5 ccw(c265,92.5) 269,92.5 ccw(c265,92.5)
RDIS on TOP "TOP15" (solid, pour order 128): 226.05,108.3 cw(c226.05,108.45) 225.9,108.45 225.9,109.494 ccw(c224.15,109.494) 225.716,110.275 cw(c225.85,110.342) 225.7,110.342 225.7,111.05 cw(c226.2,111.05) 226.2,111.55 228.8,111.55 cw(c228.8,111.05) 229.3,111.05 229.3,108.45 cw(c229.15,108.45) 229.15,108.3
RDIS on TOP "TOP16" (solid, pour order 129): 59 vertices, not listed, extent 205.7,109.95 249.3,122.15
RDIS on TOP "TOP17" (solid, pour order 130): 246.05,108.3 cw(c246.05,108.45) 245.9,108.45 245.9,109.494 ccw(c244.15,109.494) 245.716,110.275 cw(c245.85,110.342) 245.7,110.342 245.7,111.05 cw(c246.2,111.05) 246.2,111.55 248.8,111.55 cw(c248.8,111.05) 249.3,111.05 249.3,108.45 cw(c249.15,108.45) 249.15,108.3
VDD20_A on TOP "TOP18" (solid, pour order 131): 21 vertices, not listed, extent 24,132.5 30.3,143.45
GND_F on TOP "TOP19" (solid, pour order 132): 261,160 ccw(c265,160) 269,160 ccw(c265,160)
M on TOP "TOP20" (solid, pour order 133): 177.15,96 ccw(c178.5,96) 179.85,96 ccw(c178.5,96)
M on TOP "TOP21" (solid, pour order 134): 177.15,134 ccw(c178.5,134) 179.85,134 ccw(c178.5,134)
L3f on TOP "TOP22" (solid, pour order 135): 179.135,34.365 cw(c179.241,34.471) 179.183,34.61 192.9,40.291 cw(c192.958,40.153) 193.108,40.153 193.108,34.308 cw(c192.958,34.308) 193.015,34.169 183.431,30.2 cw(c183.374,30.338) 183.268,30.232
SIGN00220 on TOP "TOP23" (solid, pour order 136): 18 vertices, not listed, extent 71.6,117.5 81.15,128.15
SIGN00227 on TOP "TOP24" (solid, pour order 137): 29.962,147.25 cw(c29.962,147.4) 29.856,147.294 28.6,148.55 24.9,148.55 cw(c24.9,149.05) 24.4,149.05 24.4,154.5 cw(c24.9,154.5) 24.9,155 35.85,155 cw(c35.85,154.5) 36.35,154.5 36.35,147.75 cw(c35.85,147.75) 35.85,147.25
VP_DC on TOP "TOP26" (solid, pour order 139): 19 vertices, not listed, extent 56.65,140.6 67.85,146.46
SIGN00225 on TOP "TOP27" (solid, pour order 140): 27 vertices, not listed, extent 50.6,111.485 68.1,135.15
SIGN00122 on TOP "TOP28" (solid, pour order 141): 68 vertices, not listed, extent 49.5,38.5 76,108
L1r on TOP "TOP29" (solid, pour order 142): 17 vertices, not listed, extent 39.9,21 52.7,35
VP_DC on TOP "TOP30" (solid, pour order 143): 25 vertices, not listed, extent 39.9,38.5 46,70.5
VP_DC on TOP "TOP31" (solid, pour order 144): 73.5,152.3 cw(c73.5,152.8) 73,152.8 73,156.7 cw(c73.5,156.7) 73.5,157.2 88.453,157.2 cw(c88.453,157.05) 88.559,157.156 89.906,155.809 cw(c89.8,155.703) 89.95,155.703 89.95,152.8 cw(c89.45,152.8) 89.45,152.3
GND_DC on TOP "TOP32" (solid, pour order 145): 21 vertices, not listed, extent 73.25,124.9 89.75,134.5
L1r on TOP "TOP33" (solid, pour order 146): 81.861,30.35 cw(c81.861,30.5) 81.755,30.394 74.411,37.737 ccw(c73.174,36.5) 74.257,37.874 cw(c74.35,37.992) 74.2,37.992 74.2,49.35 cw(c74.35,49.35) 74.35,49.5 99.85,49.5 cw(c99.85,49.35) 100,49.35 100,46.211 cw(c99.85,46.211) 99.956,46.105 84.245,30.394 cw(c84.139,30.5) 84.139,30.35
L3r on TOP "TOP34" (solid, pour order 147): 42 vertices, not listed, extent 56.201,21 110.3,46.5
L3r on TOP "TOP35" (solid, pour order 148): 123.55,41.5 cw(c123.55,41.65) 123.4,41.65 123.4,44.024 ccw(c121.65,44.024) 122.888,45.261 122.887,45.261 117.394,50.755 cw(c117.5,50.861) 117.35,50.861 117.35,55.05 cw(c117.5,55.05) 117.5,55.2 123.401,55.2 cw(c123.401,55.05) 123.459,55.189 130.857,52.124 cw(c130.8,51.985) 130.95,51.985 130.95,41.65 cw(c130.8,41.65) 130.8,41.5
VP_DC on TOP "TOP36" (solid, pour order 149): 20 vertices, not listed, extent 79.15,70.94 118.2,89.65
M on TOP "TOP37" (solid, pour order 150): 17 vertices, not listed, extent 112.65,110.65 117.4,121.35
GND_DC on TOP "TOP38" (solid, pour order 151): 18 vertices, not listed, extent 112.798,124.817 145.15,164
GND_DC on TOP "TOP39" (solid, pour order 152): 58 vertices, not listed, extent 64.17,85.5 145.15,127.2
L1r on TOP "TOP40" (solid, pour order 153): 33 vertices, not listed, extent 134.45,33.393 171,59
GND_F on TOP "TOP41" (solid, pour order 154): 26 vertices, not listed, extent 102.1,21 165.5,28.999
L2r on TOP "TOP42" (solid, pour order 155): 80 vertices, not listed, extent 57.2,33.4 183,73.6
M on TOP "TOP43" (solid, pour order 156): 17 vertices, not listed, extent 167.5,93.15 181.35,136.85
VP_DC on TOP "TOP44" (solid, pour order 157): 31 vertices, not listed, extent 167.3,151.809 184.244,164
L3r on TOP "TOP45" (solid, pour order 158): 41 vertices, not listed, extent 143.4,29.8 193.108,50.261
L3f on TOP "TOP46" (solid, pour order 159): 22 vertices, not listed, extent 168.5,26 185.345,35.375
L2f on TOP "TOP47" (solid, pour order 160): 25 vertices, not listed, extent 196.608,33.4 217.9,59.55
L2f on TOP "TOP48" (solid, pour order 161): 19 vertices, not listed, extent 224,41.05 239,49.992
L3f on TOP "TOP49" (solid, pour order 162): 75 vertices, not listed, extent 220.4,29.8 260.2,112.35
L2f on TOP "TOP50" (solid, pour order 163): 53 vertices, not listed, extent 220.05,88.65 242,112.35
L1f on TOP "TOP51" (solid, pour order 164): 107 vertices, not listed, extent 157.71,33.4 246.7,112.35
L1 on TOP "TOP52" (solid, pour order 165): 33 vertices, not listed, extent 207.25,125.65 218.75,164
L2 on TOP "TOP53" (solid, pour order 166): 41 vertices, not listed, extent 222.25,125.65 238.95,164
L3 on TOP "TOP54" (solid, pour order 167): 47 vertices, not listed, extent 237.25,125.65 260.2,164
GND_F on TOP "TOP55" (solid, pour order 168): 61 vertices, not listed, extent 182.044,21 269,164
VDD20_A on TOP "TOP2" (solid, pour order 115): 21 vertices, not listed, extent 26.2,100.1 30.6,105.8
VDD20_A on TOP "TOP25" (solid, pour order 138): 22.277,50.7 cw(c22.277,50.85) 22.198,50.722 ccw(c21.75,50) 22.102,50.774 cw(c22.164,50.91) 22.062,50.8 cw(c22.062,50.95) 22.016,50.808 ccw(c21.75,50) 21.92,50.833 cw(c21.95,50.98) 21.8,50.98 cw(c21.85,51.121) 21.7,51.121 21.7,55.3 cw(c22.2,55.3) 22.2,55.8 23.9,55.8 cw(c23.9,55.3) 24.4,55.3 24.4,51.2 cw(c23.9,51.2) 23.9,50.7
GND_A on TOP "TOP56" (solid, pour order 169): 52 vertices, not listed, extent 21,29.988 43.8,143.35
GND_F on Mid-Layer 1 "MID157" (solid, pour order 78): 141,25 ccw(c145,25) 149,25 ccw(c145,25)
GND_F on Mid-Layer 1 "MID158" (solid, pour order 79): 162.65,21 cw(c162.65,21.15) 162.5,21.15 162.5,22.85 cw(c162.65,22.85) 162.65,23 185.85,23 cw(c185.85,22.85) 186,22.85 186,21.15 cw(c185.85,21.15) 185.85,21
GND_F on Mid-Layer 1 "MID159" (solid, pour order 80): 261,25 ccw(c265,25) 269,25 ccw(c265,25)
GND_F on Mid-Layer 1 "MID160" (solid, pour order 81): 261,92.5 ccw(c265,92.5) 269,92.5 ccw(c265,92.5)
RDIS on Mid-Layer 1 "MID161" (solid, pour order 82): 59 vertices, not listed, extent 205.7,109.95 249.3,122.15
GND_DC on Mid-Layer 1 "MID162" (solid, pour order 83): 89.25,118.4 cw(c89.25,119) 88.826,118.576 86.328,121.074 86.326,121.076 86.325,121.076 cw(c86.75,121.5) 86.15,121.503 86.15,123 cw(c86.75,123) 86.75,123.6 99.1,123.6 cw(c99.1,123.1) 99.6,123.1 99.6,119 cw(c99,119) 99,118.4
GND_F on Mid-Layer 1 "MID163" (solid, pour order 84): 261,160 ccw(c265,160) 269,160 ccw(c265,160)
VP_DC on Mid-Layer 1 "MID164" (solid, pour order 85): 99.25,134.2 cw(c99.25,135) 98.45,135 98.45,139.3 cw(c99.25,139.3) 99.25,140.1 106.95,140.1 cw(c106.95,139.95) 107.1,139.95 107.1,137.25 cw(c106.95,137.25) 106.95,137.1 104.475,137.1 104.025,136.65 cw(c103.4,137.15) 103.966,136.584 101.816,134.434 cw(c101.25,135) 101.246,134.2
L3f on Mid-Layer 1 "MID165" (solid, pour order 86): 179.135,34.365 cw(c179.241,34.471) 179.183,34.61 192.9,40.291 cw(c192.958,40.153) 193.108,40.153 193.108,34.308 cw(c192.958,34.308) 193.015,34.169 183.431,30.2 cw(c183.374,30.338) 183.268,30.232
GND_A on Mid-Layer 1 "MID166" (solid, pour order 87): 23 vertices, not listed, extent 21,29.999 43.8,147.96
L1r on Mid-Layer 1 "MID167" (solid, pour order 88): 17 vertices, not listed, extent 39.9,21 52.7,35
VP_DC on Mid-Layer 1 "MID168" (solid, pour order 89): 28 vertices, not listed, extent 39.9,38.5 46,70.5
VP_DC on Mid-Layer 1 "MID169" (solid, pour order 90): 25 vertices, not listed, extent 56.65,140.6 103.9,157.2
GND_DC on Mid-Layer 1 "MID170" (solid, pour order 91): 19 vertices, not listed, extent 73.25,126.7 89.75,134.5
SIGN00122 on Mid-Layer 1 "MID171" (solid, pour order 92): 64 vertices, not listed, extent 49.3,38.5 76,108
L1r on Mid-Layer 1 "MID172" (solid, pour order 93): 81.861,30.35 cw(c81.861,30.5) 81.755,30.394 74.411,37.737 ccw(c73.174,36.5) 74.257,37.874 cw(c74.35,37.992) 74.2,37.992 74.2,49.35 cw(c74.35,49.35) 74.35,49.5 99.85,49.5 cw(c99.85,49.35) 100,49.35 100,46.211 cw(c99.85,46.211) 99.956,46.105 84.245,30.394 cw(c84.139,30.5) 84.139,30.35
L3r on Mid-Layer 1 "MID173" (solid, pour order 94): 33 vertices, not listed, extent 56.201,21 110.3,46.5
L3r on Mid-Layer 1 "MID174" (solid, pour order 95): 123.55,41.5 cw(c123.55,41.65) 123.4,41.65 123.4,44.024 ccw(c121.65,44.024) 122.888,45.261 122.887,45.261 117.394,50.755 cw(c117.5,50.861) 117.35,50.861 117.35,55.05 cw(c117.5,55.05) 117.5,55.2 123.401,55.2 cw(c123.401,55.05) 123.459,55.189 130.857,52.124 cw(c130.8,51.985) 130.95,51.985 130.95,41.65 cw(c130.8,41.65) 130.8,41.5
GND_F on Mid-Layer 1 "MID175" (solid, pour order 96): 26 vertices, not listed, extent 102.1,21 165.5,28.999
L3f on Mid-Layer 1 "MID176" (solid, pour order 97): 22 vertices, not listed, extent 168.5,26 185.345,35.375
L3r on Mid-Layer 1 "MID177" (solid, pour order 98): 41 vertices, not listed, extent 143.4,29.8 193.108,50.261
L1r on Mid-Layer 1 "MID178" (solid, pour order 99): 35 vertices, not listed, extent 134.45,33.393 171,59
L2r on Mid-Layer 1 "MID179" (solid, pour order 100): 79 vertices, not listed, extent 57.2,33.4 183,73.6
L2f on Mid-Layer 1 "MID180" (solid, pour order 101): 25 vertices, not listed, extent 196.608,33.4 217.9,59.55
L2f on Mid-Layer 1 "MID181" (solid, pour order 102): 19 vertices, not listed, extent 224,41.05 239,49.992
L2f on Mid-Layer 1 "MID182" (solid, pour order 103): 35 vertices, not listed, extent 220.05,88.65 242,112.35
L1f on Mid-Layer 1 "MID183" (solid, pour order 104): 95 vertices, not listed, extent 157.71,33.4 246.7,112.35
GND_DC on Mid-Layer 1 "MID184" (solid, pour order 105): 22 vertices, not listed, extent 112.8,147.1 145.15,164
GND_DC on Mid-Layer 1 "MID185" (solid, pour order 106): 66 vertices, not listed, extent 64.17,85.5 145.15,136.85
M on Mid-Layer 1 "MID186" (solid, pour order 107): 35 vertices, not listed, extent 112.65,93.15 181.35,136.85
VP_DC on Mid-Layer 1 "MID187" (solid, pour order 108): 56 vertices, not listed, extent 79.15,70.94 193.25,164
L1 on Mid-Layer 1 "MID188" (solid, pour order 109): 33 vertices, not listed, extent 207.25,125.65 218.75,164
L2 on Mid-Layer 1 "MID189" (solid, pour order 110): 41 vertices, not listed, extent 222.25,125.65 238.95,164
L3 on Mid-Layer 1 "MID190" (solid, pour order 111): 47 vertices, not listed, extent 237.25,125.65 260.2,164
L3f on Mid-Layer 1 "MID191" (solid, pour order 112): 62 vertices, not listed, extent 220.4,29.8 260.2,112.35
GND_F on Mid-Layer 1 "MID192" (solid, pour order 113): 60 vertices, not listed, extent 182.043,21 269,164
GND_F on Mid-Layer 2 "MID295" (solid, pour order 42): 141,25 ccw(c145,25) 149,25 ccw(c145,25)
GND_F on Mid-Layer 2 "MID296" (solid, pour order 43): 261,25 ccw(c265,25) 269,25 ccw(c265,25)
GND_F on Mid-Layer 2 "MID297" (solid, pour order 44): 261,92.5 ccw(c265,92.5) 269,92.5 ccw(c265,92.5)
RDIS on Mid-Layer 2 "MID298" (solid, pour order 45): 59 vertices, not listed, extent 205.7,109.95 249.3,122.15
VP_DC on Mid-Layer 2 "MID299" (solid, pour order 46): 99.25,134.2 cw(c99.25,135) 98.45,135 98.45,137 cw(c99.25,137) 99.25,137.8 101.25,137.8 cw(c101.25,137) 102.05,137 102.05,135 cw(c101.25,135) 101.25,134.2
GND_F on Mid-Layer 2 "MID2100" (solid, pour order 47): 261,160 ccw(c265,160) 269,160 ccw(c265,160)
GND_DC on Mid-Layer 2 "MID2101" (solid, pour order 48): 89.25,118.4 cw(c89.25,119) 88.826,118.576 86.328,121.074 86.326,121.076 86.325,121.076 cw(c86.75,121.5) 86.15,121.503 86.15,123 cw(c86.75,123) 86.75,123.6 99.1,123.6 cw(c99.1,123.1) 99.6,123.1 99.6,119 cw(c99,119) 99,118.4
GND_F on Mid-Layer 2 "MID2102" (solid, pour order 49): 160.35,21 cw(c160.35,21.15) 160.2,21.15 160.2,22.85 cw(c160.35,22.85) 160.35,23 185.85,23 cw(c185.85,22.85) 186,22.85 186,21.15 cw(c185.85,21.15) 185.85,21
VP_DC on Mid-Layer 2 "MID2105" (solid, pour order 52): 19 vertices, not listed, extent 56.65,140.6 67.05,146.46
VP_DC on Mid-Layer 2 "MID2106" (solid, pour order 53): 73.5,152.3 cw(c73.5,152.8) 73,152.8 73,156.7 cw(c73.5,156.7) 73.5,157.2 88.453,157.2 cw(c88.453,157.05) 88.559,157.156 89.906,155.809 cw(c89.8,155.703) 89.95,155.703 89.95,152.8 cw(c89.45,152.8) 89.45,152.3
GND_DC on Mid-Layer 2 "MID2107" (solid, pour order 54): 19 vertices, not listed, extent 73.25,126.7 89.75,134.5
SIGN00122 on Mid-Layer 2 "MID2108" (solid, pour order 55): 21 vertices, not listed, extent 50.6,80.14 63.17,108
SIGN00122 on Mid-Layer 2 "MID2109" (solid, pour order 56): 46 vertices, not listed, extent 49.5,38.5 78,67.44
L3r on Mid-Layer 2 "MID2110" (solid, pour order 57): 19 vertices, not listed, extent 56.2,30.2 70.7,35
L2r on Mid-Layer 2 "MID2111" (solid, pour order 58): 113.95,33.4 cw(c113.95,33.55) 113.8,33.55 113.8,37.756 cw(c113.95,37.756) 113.95,37.906 116.839,37.906 116.843,37.906 119.257,37.906 cw(c119.257,37.756) 119.348,37.875 cw(c118.05,36.161) 119.877,37.294 cw(c119.75,37.215) 119.9,37.215 119.9,35.108 119.9,35.104 119.9,33.55 cw(c119.75,33.55) 119.75,33.4
L1r on Mid-Layer 2 "MID2112" (solid, pour order 59): 17 vertices, not listed, extent 134.45,33.393 139.9,37.906
GND_F on Mid-Layer 2 "MID2113" (solid, pour order 60): 21 vertices, not listed, extent 102.1,21 163.759,28.999
L1r on Mid-Layer 2 "MID2114" (solid, pour order 61): 57 vertices, not listed, extent 39.9,21 171,64.4
L3r on Mid-Layer 2 "MID2115" (solid, pour order 62): 48 vertices, not listed, extent 102.45,29.8 193.108,55.2
L3f on Mid-Layer 2 "MID2116" (solid, pour order 63): 22 vertices, not listed, extent 168.5,26 185.345,35.375
L2r on Mid-Layer 2 "MID2117" (solid, pour order 64): 64 vertices, not listed, extent 57.2,53.005 183,73.6
L2f on Mid-Layer 2 "MID2118" (solid, pour order 65): 19 vertices, not listed, extent 202.45,33.4 207.95,38.05
L1f on Mid-Layer 2 "MID2119" (solid, pour order 66): 211.6,33.4 cw(c211.6,33.55) 211.45,33.55 211.45,37.9 cw(c211.6,37.9) 211.6,38.05 214.034,38.05 214.036,38.05 215.757,38.05 cw(c215.757,38) 215.792,38.035 216.885,36.942 cw(c216.85,36.907) 216.9,36.907 216.9,35.08 216.9,35.077 216.9,33.55 cw(c216.75,33.55) 216.75,33.4
L1f on Mid-Layer 2 "MID2120" (solid, pour order 67): 234.9,83.15 cw(c234.9,83.3) 234.75,83.3 234.75,89.4 cw(c234.9,89.4) 234.9,89.55 238.8,89.55 cw(c238.8,89.4) 238.95,89.4 238.95,86.511 238.95,86.509 238.95,84.291 238.95,84.289 238.95,83.3 cw(c238.8,83.3) 238.8,83.15
L2f on Mid-Layer 2 "MID2121" (solid, pour order 68): 73 vertices, not listed, extent 196.608,41.05 246.7,112.35
L1f on Mid-Layer 2 "MID2122" (solid, pour order 69): 53 vertices, not listed, extent 157.71,62.479 233.2,112.35
L3f on Mid-Layer 2 "MID2123" (solid, pour order 70): 101 vertices, not listed, extent 179.091,29.8 260.2,112.35
L3 on Mid-Layer 2 "MID2124" (solid, pour order 71): 47 vertices, not listed, extent 237.25,125.65 260.2,164
L2 on Mid-Layer 2 "MID2125" (solid, pour order 72): 41 vertices, not listed, extent 222.25,125.65 238.95,164
L1 on Mid-Layer 2 "MID2126" (solid, pour order 73): 33 vertices, not listed, extent 207.25,125.65 218.75,164
GND_F on Mid-Layer 2 "MID2127" (solid, pour order 74): 60 vertices, not listed, extent 182.043,21 269,164
GND_DC on Mid-Layer 2 "MID2128" (solid, pour order 75): 74 vertices, not listed, extent 64.17,85.5 145.15,164
M on Mid-Layer 2 "MID2129" (solid, pour order 76): 35 vertices, not listed, extent 112.65,93.15 181.35,136.85
VP_DC on Mid-Layer 2 "MID2130" (solid, pour order 77): 84 vertices, not listed, extent 39.9,38.5 193.25,164
VDD20_A on Mid-Layer 2 "MID293" (solid, pour order 40): 27.5,131 cw(c27.5,131.15) 27.35,131.15 27.35,135.386 cw(c27.5,135.386) 27.394,135.492 27.824,135.922 cw(c28.25,135.5) 28.25,136.1 29.75,136.1 cw(c29.75,135.5) 30.35,135.5 30.35,134 cw(c29.75,134) 30.172,133.574 28.85,132.251 28.85,131.15 cw(c28.7,131.15) 28.7,131
VDD20_A on Mid-Layer 2 "MID294" (solid, pour order 41): 20 vertices, not listed, extent 26.15,97.351 28.85,105
GND_A on Mid-Layer 2 "MID2103" (solid, pour order 50): 19 vertices, not listed, extent 21,30 43.8,147.96
VDD20_A on Mid-Layer 2 "MID2104" (solid, pour order 51): 18 vertices, not listed, extent 22.35,50.7 24.6,57.05
GND_F on BOTTOM "BOTTOM131" (solid, pour order 2): 261,160 ccw(c265,160) 269,160 ccw(c265,160)
GND_F on BOTTOM "BOTTOM132" (solid, pour order 3): 261,92.5 ccw(c265,92.5) 269,92.5 ccw(c265,92.5)
GND_F on BOTTOM "BOTTOM133" (solid, pour order 4): 261,25 ccw(c265,25) 269,25 ccw(c265,25)
GND_F on BOTTOM "BOTTOM134" (solid, pour order 5): 141,25 ccw(c145,25) 149,25 ccw(c145,25)
RDIS on BOTTOM "BOTTOM135" (solid, pour order 6): 59 vertices, not listed, extent 205.7,109.95 249.3,122.15
VP_DC on BOTTOM "BOTTOM136" (solid, pour order 7): 99.25,134.2 cw(c99.25,135) 98.45,135 98.45,137 cw(c99.25,137) 99.25,137.8 101.25,137.8 cw(c101.25,137) 102.05,137 102.05,135 cw(c101.25,135) 101.25,134.2
GND_DC on BOTTOM "BOTTOM137" (solid, pour order 8): 17 vertices, not listed, extent 86.2,118.45 104.45,125.047
GND_F on BOTTOM "BOTTOM140" (solid, pour order 11): 160.65,21 cw(c160.65,21.15) 160.5,21.15 160.5,22.85 cw(c160.65,22.85) 160.65,23 185.85,23 cw(c185.85,22.85) 186,22.85 186,21.15 cw(c185.85,21.15) 185.85,21
L3r on BOTTOM "BOTTOM143" (solid, pour order 14): 56.695,30.2 56.692,30.2 cw(c56.7,30.7) 56.2,30.692 56.2,30.695 56.2,34.85 cw(c56.35,34.85) 56.35,35 70.55,35 cw(c70.55,34.85) 70.7,34.85 70.7,30.35 cw(c70.55,30.35) 70.55,30.2
SIGN00122 on BOTTOM "BOTTOM144" (solid, pour order 15): 21 vertices, not listed, extent 50.6,80.14 63.17,108
VP_DC on BOTTOM "BOTTOM145" (solid, pour order 16): 20 vertices, not listed, extent 56.65,140.6 67.05,146.46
